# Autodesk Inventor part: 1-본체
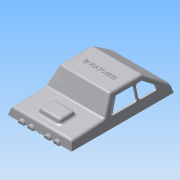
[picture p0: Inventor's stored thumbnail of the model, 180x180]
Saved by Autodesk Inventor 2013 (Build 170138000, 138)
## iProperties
Created: 2015-06
Part Number: 1-본체
Material: ABS 플라스틱
Document SubType Name: Modeling
Designer: Administrator
Density: 1.06 g/cm^3
Mass: 33.4714 g
Surface Area: 313.849 cm^2
Volume: 31.5768 cm^3
Author: Administrator
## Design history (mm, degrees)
sketch "스케치1"
  geometry: L1 (0, 0)-(122, 0); L2 (0, 0)-(2.412, 9); L3 (42, 11.075)-(53.826, 30); L4 (53.826, 30)-(92, 30); L5 (92, 30)-(119.321, 10); L6 (119.321, 10)-(122, 0); L7 (2.412, 9)-(42, 11.075)
  constraints: 14 end point, 1 horizontal, 1 parallel
  dimensions: "d1" = 105 deg angle of L1 L2; "d2" = 105 deg angle of L1 L6; "d5" = 30 distance between parallel lines of L1 L4; "d6" = 20 distance from line of L5.end L4; "d10" = 3 deg angle of L1 L7; "d11" = 125 deg angle of L7 L3; "d12" = 42 horizontal distance of L3.start L1.start; "d13" = 9 vertical distance of L1.start L2.end; "d26" = 122 distance of L1.start L1.end; "d40" = 30 horizontal distance of L1.end L4.end
extrude "돌출1" new body sketch "스케치1" stored distance "d14" = 76; taper "d15" = 0 deg
sketch "스케치2"
  geometry: L1 (28.121, 51)-(8.121, 51); L2 (8.121, 51)-(8.121, 25); L3 (8.121, 25)-(28.121, 25); L4 (28.121, 25)-(28.121, 51); L5 (-2.879, 0)-(-2.879, 76) reference; 2 further points
  constraints: 8 end point, 2 parallel, 1 horizontal, 1 horizontal alignment, 1 midpoint, 1 perpendicular
  dimensions: "d16" = 20 distance of L1.start L1.end; "d18" = 26 distance of L3.end L1.start; "d19" = 11 distance between parallel lines of L5 L2
extrude "돌출2" join sketch "스케치2" distance "d20" = 5; taper "d21" = 0 deg
sketch "스케치4"
  geometry: L1 (30, -38)-(30, 38) reference; L2 (0, 38)-(0, -38) reference; L3 (30, 38)-(11.075, 38) reference; L4 (11.075, 38)-(9, 38) reference; L5 (9, 38)-(0, 38) reference; L6 (11.075, -38)-(30, -38) reference; L7 (0, -38)-(9, -38) reference; L8 (9, -38)-(11.075, -38) reference; L9 (0, 38)-(30, 29.962); L10 (0, -38)-(30, -29.962); 1 further point
  constraints: 4 end point, 2 point on line
  dimensions: "d27" = 105 deg angle of L2 L9; "d28" = 105 deg angle of L2 L10
extrude "돌출3" cut sketch "스케치4" distance "d29" = 130; taper "d30" = 0 deg
sketch "스케치7"
  geometry: 1 further point
feature "쉘2" dims "d61" = 2
sketch "스케치11"
  geometry: L1 (119.929, -2.071)-(119.929, -73.929) reference; L2 (119.929, -73.929)-(2.071, -73.929) reference; L3 (2.071, -73.929)-(2.071, -2.071) reference; L4 (2.071, -2.071)-(119.929, -2.071) reference; L5 (122, -76)-(122, 0) reference; L6 (0, 0)-(122, 0) reference; L7 (0, 0)-(0, -76) reference; L8 (122, -76)-(0, -76) reference; L9 (1, -1)-(121, -1); L10 (121, -1)-(121, -75); L11 (121, -75)-(1, -75); L12 (1, -75)-(1, -1); 1 further point
  constraints: 8 end point, 2 parallel, 1 horizontal, 1 perpendicular
  dimensions: "d77" = 1 distance between parallel lines of L10 L5; "d78" = 1 distance between parallel lines of L9 L6; "d79" = 1 distance between parallel lines of L12 L7; "d80" = 1 distance between parallel lines of L11 L8
extrude "돌출8" join sketch "스케치11" distance "d81" = 1; taper "d82" = 0 deg
sketch "스케치12"
  geometry: L1 (42, 11.075)-(53.826, 30) reference; L2 (53.826, 30)-(92, 30) reference; L3 (92, 30)-(119.321, 10) reference; L4 (47.224, 10)-(56.597, 25); L5 (90.365, 25)-(110.856, 10); L6 (56.597, 25)-(81.224, 25); L7 (81.224, 25)-(81.224, 10); L8 (81.224, 10)-(47.224, 10); L9 (90.365, 25)-(82.856, 25); L10 (82.856, 25)-(82.856, 10); L11 (82.856, 10)-(110.856, 10); 1 further point
  constraints: 16 end point, 4 parallel, 2 perpendicular
  dimensions: "d84" = 5 distance between parallel lines of L3 L5; "d85" = 5 distance between parallel lines of L4 L1; "d86" = 5 distance between parallel lines of L6 L2; "d87" = 5 distance between parallel lines of L9 L2; "d88" = 34 distance of L7.end L4.start; "d89" = 28 distance of L10.end L5.end; "d90" = 15 vertical distance of L4.start L4.end; "d91" = 15 vertical distance of L5.start L5.end
extrude "돌출9" cut sketch "스케치12" stored distance "d92" = 1; taper "d93" = 0 deg
node "작업 평면1"
sketch "스케치13"
  geometry: A1 r 4 centre (0, -10) between (0, -6) and (0, -14); A2 r 4 centre (0, -21) between (0, -17) and (0, -25); A3 r 4 centre (0, 10) between (0, 14) and (0, 6); A4 r 4 centre (0, 21) between (0, 25) and (0, 17); 3 further points
  constraints: 8 point on circle, 4 centre point, 3 equal radius, 13 other
  dimensions: "d95" = 4 radius of A2; "d97" = 20 distance of A3.centre A1.centre; "d98" = 11 distance of A1.centre A2.centre; "d99" = 11 distance of A4.centre A3.centre; "d100" = 10 distance of point (0, 0) A3.centre
extrude "돌출10" join sketch "스케치13" stored distance "d101" = 1; taper "d102" = 0 deg
sketch "스케치14"
  geometry: L1 (68.174, 8.038)-(68.174, -67.962) reference; 2 further points
  constraints: 1 horizontal alignment, 1 other
  dimensions: "d103" = 50 distance from line of L1 point (18.174, -29.962)
feature "엠보싱1" sketch "스케치14" dims "d104" = 0.5, "d105" = 0
sketch "스케치15"
  geometry: L1 (122, 0)-(122, 76) reference; L2 (1, 75)-(1, 1) reference; C1 r 3 at (21, 38); C2 r 3 at (61, 60); C3 r 3 at (61, 16); C4 r 3 at (101, 38); 2 further points
  constraints: 4 centre point, 3 equal radius, 2 horizontal alignment, 1 midpoint, 1 vertical alignment
  dimensions: "d106" = 6 diameter of C1; "d108" = 21 distance from line of L1 C4.centre; "d109" = 40 horizontal distance of C4.centre C2.centre; "d110" = 40 horizontal distance of C2.centre C1.centre; "d111" = 44 distance of C3.centre C2.centre; "d112" = 22 vertical distance of C3.centre C1.centre
extrude "돌출11" join sketch "스케치15" stored distance "d113" = 1; taper "d114" = 2 deg
sketch "스케치16"
  geometry: L1 (30.494, 10.472)-(30.232, 15.465) reference; L2 (10.521, 9.425)-(10.259, 14.418) reference; L3 (10.259, 14.418)-(30.232, 15.465) reference; L4 (30.494, 10.472)-(28.415, 15.37); L5 (10.521, 9.425)-(12.077, 14.513); L6 (2.412, 9)-(42, 11.075) reference; 1 further point
  constraints: 4 end point, 2 point on line
  dimensions: "d115" = 70 deg angle of L6 L4; "d116" = 70 deg angle of L5 L6
extrude "돌출12" cut sketch "스케치16" stored distance "d117" = 1; taper "d118" = 0 deg
sketch "스케치18"
  geometry: L1 (0, 0)-(122, 0) reference; L2 (24, 0)-(24.46, 13.16) reference; L3 (18, 0)-(17.553, 12.798) reference; L4 (12.361, 12.526)-(28.339, 13.363) reference; L5 (14.653, 12.646)-(16.53, 2); L6 (16.53, 2)-(25.47, 2); L7 (25.47, 2)-(27.465, 13.317); L8 (21, 2)-(21, 12.978)
  constraints: 8 end point, 3 point on line, 1 midpoint, 1 parallel, 1 perpendicular
  dimensions: "d124" = 3 distance from line of L3.start L8; "d125" = 20 deg angle of L5 L7; "d126" = 80 deg angle of L6 L5; "d127" = 2 distance between parallel lines of L1 L6; "d128" = 11.31711 vertical distance of L6.end L7.end
extrude "돌출13" join sketch "스케치18" stored distance "d129" = 2; taper "d130" = 0 deg
sketch "스케치19"
  geometry: L1 (0, 0)-(2, 0) reference; L2 (2, 10.81)-(2, 0) reference; L3 (0, 10.81)-(2, 10.81) reference; L4 (0, 0)-(0, 10.81) reference; L5 (0, 0)-(-0.472, 10.81); L6 (-0.472, 10.81)-(2.472, 10.81); L7 (2.472, 10.81)-(2, 0); 1 further point
  constraints: 6 end point, 1 horizontal, 1 point on line
  dimensions: "d131" = 5 deg angle of L7 L5; "d132" = 87.5 deg angle of L1 L5
extrude "돌출14" join sketch "스케치19" stored distance "d133" = 2; taper "d134" = 0 deg
sketch "스케치20"
  geometry: L1 (0, 0)-(2, 0) reference; L2 (0, -11.492)-(0, 0) reference; L3 (2, -11.492)-(0, -11.492) reference; L4 (2, 0)-(2, -11.492) reference; L5 (0, -11.492)-(-0.502, 0); L6 (-0.502, 0)-(2.502, 0); L7 (2.502, 0)-(2, -11.492); 1 further point
  constraints: 6 end point, 1 horizontal, 1 point on line
  dimensions: "d135" = 87.5 deg angle of L3 L5; "d136" = 5 deg angle of L7 L5
extrude "돌출15" join sketch "스케치20" stored distance "d137" = 2; taper "d138" = 0 deg
sketch "스케치22"
  geometry: L1 (91.346, 28)-(117.571, 8.802) reference; L2 (92, 30)-(119.321, 10) reference; L3 (0, 0)-(122, 0) reference; L4 (93.344, 2)-(108.656, 2); L5 (108.656, 2)-(111.124, 16); L6 (54.934, 28)-(91.346, 28) reference; L7 (93.344, 2)-(88.407, 30); L8 (101, 2)-(101, 23.412); L9 (98, 0)-(97.171, 23.736) reference; L10 (104, 0)-(104.638, 18.27) reference; L11 (53.826, 30)-(92, 30) reference
  constraints: 8 end point, 3 point on line, 1 midpoint, 1 parallel, 1 perpendicular
  dimensions: "d139" = 3 horizontal distance of L9.start L8.start; "d140" = 80 deg angle of L4 L7; "d141" = 20 deg angle of L5 L7; "d142" = 2 distance between parallel lines of L3 L4; "d143" = 14 vertical distance of L4.end L5.end
extrude "돌출16" join sketch "스케치22" stored distance "d144" = 2; taper "d145" = 0 deg
sketch "스케치23"
  geometry: L1 (0, 0)-(2, 0) reference; L2 (0, -26.401)-(0, 0) reference; L3 (0, -26.401)-(2, -26.401) reference; L4 (2, 0)-(2, -26.401) reference; L5 (0, -26.401)-(-1.153, 0); L6 (-1.153, 0)-(3.153, 0); L7 (3.153, 0)-(2, -26.401); 2 further points
  constraints: 6 end point, 2 midpoint, 1 equal length, 1 perpendicular
  dimensions: "d146" = 87.5 deg angle of L3 L5
extrude "돌출17" join sketch "스케치23" stored distance "d147" = 2; taper "d148" = 0 deg
sketch "스케치24"
  geometry: L1 (0, 0)-(2, 0) reference; L2 (0, -11.987)-(0, 0) reference; L3 (2, -11.987)-(0, -11.987) reference; L4 (2, 0)-(2, -11.987) reference; L5 (0, -11.987)-(-0.523, 0); L6 (-0.523, 0)-(2.523, 0); L7 (2.523, 0)-(2, -11.987); 1 further point
  constraints: 6 end point, 1 equal length, 1 horizontal, 1 point on line
  dimensions: "d149" = 87.5 deg angle of L3 L5
extrude "돌출18" join sketch "스케치24" stored distance "d150" = 2; taper "d151" = 0 deg
node "작업 평면2"
sketch "스케치25"
  geometry: L1 (0, 0)-(122, 0) reference; L2 (42, 11.075)-(53.826, 30) reference; L3 (53.826, 30)-(92, 30) reference; L4 (58, 0)-(57.022, 28) reference; L5 (64, 0)-(64.978, 28) reference; L6 (58, 0)-(52.956, 28.608); L7 (64, 0)-(69.29, 30)
  constraints: 4 end point, 2 point on line
  dimensions: "d153" = 80 deg angle of L1 L6; "d154" = 80 deg angle of L1 L7
extrude "돌출19" join sketch "스케치25" stored distance "d155" = 2; taper "d156" = 0 deg
sketch "스케치26"
  geometry: L1 (0, 0)-(2, 0) reference; L2 (0, -26.06)-(0, 0) reference; L3 (0, -26.06)-(2, -26.06) reference; L4 (2, 0)-(2, -26.06) reference; L5 (0, -26.06)-(-1.138, 0); L6 (-1.138, 0)-(3.138, 0); L7 (3.138, 0)-(2, -26.06); 2 further points
  constraints: 6 end point, 2 midpoint, 1 equal length, 1 perpendicular
  dimensions: "d157" = 87.5 deg angle of L3 L5
extrude "돌출20" join sketch "스케치26" stored distance "d158" = 2; taper "d159" = 0 deg
node "작업 평면3"
sketch "스케치27"
  geometry: L1 (0, 0)-(2, 0) reference; L2 (0, -28.432)-(0, 0) reference; L3 (2, -28.432)-(0, -28.432) reference; L4 (2, 0)-(2, -28.432) reference; L5 (0, -28.432)-(-1.241, 0); L6 (-1.241, 0)-(3.241, 0); L7 (3.241, 0)-(2, -28.432); 2 further points
  constraints: 6 end point, 2 midpoint, 1 equal length, 1 perpendicular
  dimensions: "d161" = 87.5 deg angle of L3 L5
extrude "돌출21" join sketch "스케치27" stored distance "d162" = 2; taper "d163" = 0 deg
fillet "모깎기1" dims "d164" = 3
chamfer "모따기1" distance "d165" = 1; stored, may be unused: second distance "d166" = 2, angle "d167" = 45 deg
fillet "모깎기2" dims "d168" = 3
fillet "모깎기3" dims "d169" = 3
fillet "모깎기4" dims "d170" = 3
fillet "모깎기5" dims "d171" = 3
fillet "모깎기6" dims "d172" = 3
sketch "스케치28"
  geometry: L1 (63.828, 15)-(64, 15) reference; L2 (64, 17)-(64, 15) reference; L3 (64, 17)-(63.828, 17) reference; L4 (58.172, 17)-(58, 17) reference; L5 (58, 17)-(58, 15) reference; L6 (58, 15)-(58.172, 15) reference; C1 r 3 at (21, 38) reference; C2 r 3 at (101, 38) reference; A1 r 3 centre (61, 60) between (63.828, 61) and (58.172, 61) reference; A2 r 3 centre (61, 16) between (58.172, 15) and (63.828, 15) reference; A3 r 3 centre (61, 16) between (63.828, 17) and (58.172, 17) reference; 5 further points
  constraints: 4 coincident
hole "구멍1" sketch "스케치28" at (61, 60), (101, 38), (61, 16), (21, 38) diameter "d173" = 3.242; stored, may be unused: countersink angle "d177" = 90 deg, drill point angle "d179" = 118 deg; dims "d174" = 9, "d175" = 4, "d176" = 2, "d178" = 11
node "솔리드1"
mirror "대칭1"
node "투영된 루프1"
node "투영된 루프2"
other parameters: "d94" = -2, "d152" = 22, "d160" = -2
